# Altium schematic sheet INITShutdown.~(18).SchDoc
size A4
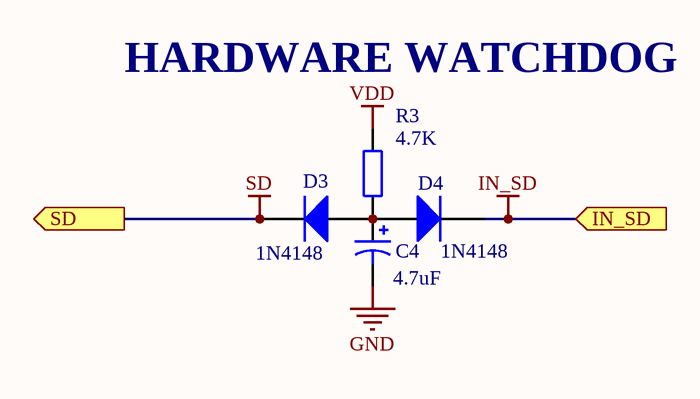
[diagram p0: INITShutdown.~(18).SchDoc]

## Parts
C4  value 4.7uF  [CAPPR2.5-6.3X5]  (hidden comment: Cap Pol1 4.7u)
D3  value 1N4148  [DO-204AL]  (hidden comment: Diode1)
D4  value 1N4148  [DO-204AL]  (hidden comment: Diode1)
R3  4.7k  [AXIAL-0.3]

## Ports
IN_SD (in), SD (out)

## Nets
GND: C4.2
IN_SD: D4.2(K) ; port IN_SD
SD: D3.2(K) ; port SD
VDD: R3.2
NetC4_1: C4.1 D3.1(A) D4.1(A) R3.1

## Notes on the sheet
- (near R3) HARDWARE WATCHDOG

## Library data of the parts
C4 = Cap Pol1: Polarized Capacitor (Radial)
D3 D4 = Diode: 1N4148
R3 = Res2: Resistor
